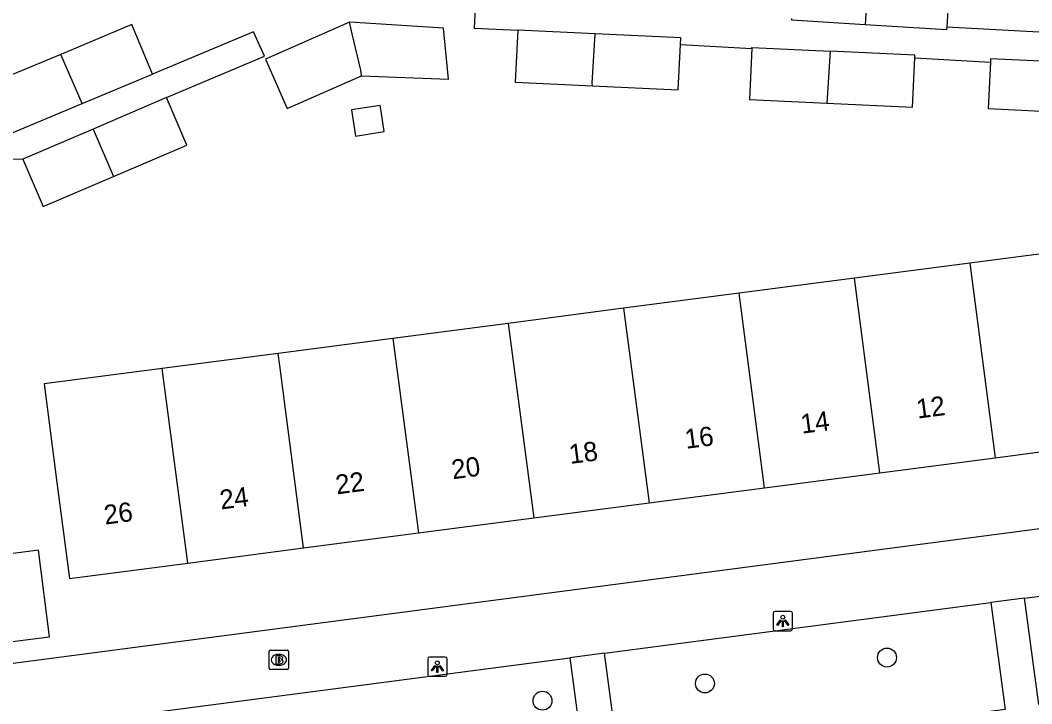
# Model space of a CAD drawing. Extents: x 162074 to 163034, y 381824 to 382557.
# Drawn here: x 162366.6 to 162418.9, y 382465.4 to 382500.7 of the extents above; entities that cross this region are included whole.
import ezdxf

# ---------------------------------------------------------------- set-up
doc = ezdxf.new("R2010")
doc.units = 0
for name, color, linetype in [('IMGEO_Boom', 7, 'Continuous'), ('IMGEO_Brandkraan', 7, 'Continuous'), ('IMGEO_Lichtpunt', 7, 'Continuous'), ('IMGEO_Pand', 7, 'Continuous'), ('IMGEO_Pand_nummerreeks', 7, 'Continuous'), ('IMGEO_Voetpad_open', 7, 'Continuous')]:
    doc.layers.add(name, color=color, linetype=linetype)

msp = doc.modelspace()

# ---------------------------------------------------------------- linework, layer by layer
at = {"layer": 'IMGEO_Boom'}
for centre in [(162411.408, 382467.759), (162401.998, 382466.42), (162393.602, 382465.53)]:
    msp.add_circle(centre, 0.489, dxfattribs=at)
at = {"layer": 'IMGEO_Brandkraan'}
for p, q in [((162379.475, 382467.216), (162379.475, 382468.068)), ((162379.55, 382468.142), (162380.402, 382468.142)), ((162380.476, 382468.068), (162380.476, 382467.216)), ((162379.963, 382467.922), (162379.988, 382467.922)), ((162380.402, 382467.142), (162379.55, 382467.142)), ((162379.986, 382467.362), (162379.961, 382467.362))]:
    msp.add_line(p, q, dxfattribs=at)
for points in [[(162379.475, 382467.216), (162379.475, 382468.068)], [(162379.55, 382468.142), (162380.402, 382468.142)], [(162380.476, 382468.068), (162380.476, 382467.216)], [(162379.823, 382467.842), (162379.823, 382467.442), (162380.036, 382467.442)], [(162380.054, 382467.842), (162379.823, 382467.842)], [(162380.002, 382467.761), (162379.948, 382467.761), (162379.948, 382467.685)], [(162379.948, 382467.685), (162380.001, 382467.685)], [(162380.01, 382467.609), (162379.948, 382467.609), (162379.948, 382467.528)], [(162379.948, 382467.528), (162380.01, 382467.528)], [(162380.402, 382467.142), (162379.55, 382467.142)]]:
    msp.add_lwpolyline(points, dxfattribs=at)
for centre, radius, start, end in [((162379.552, 382468.066), 0.0765, 91.552, 178.448), ((162379.552, 382468.066), 0.0765, 91.552, 178.448), ((162380.4, 382468.066), 0.0765, 1.552, 88.448), ((162380.4, 382468.066), 0.0765, 1.552, 88.448), ((162380.003, 382467.723), 0.0379, 267.8285, 90.9355), ((162380.011, 382467.568), 0.0404, 269.8759, 90.5077), ((162380.042, 382467.693), 0.251, 268.6676, 293.5347), ((162380.058, 382467.697), 0.145, 59.4692, 91.5367), ((162380.083, 382467.744), 0.0922, 285.5137, 58.1501), ((162380.088, 382467.552), 0.105, 301.3115, 78.989), ((162379.552, 382467.218), 0.0765, 181.552, 268.448), ((162379.552, 382467.218), 0.0765, 181.552, 268.448), ((162380.4, 382467.218), 0.0765, 271.552, 358.448), ((162380.4, 382467.218), 0.0765, 271.552, 358.448)]:
    msp.add_arc(centre, radius, start, end, dxfattribs=at)
for centre, major_axis, ratio, start_param, end_param in [((162379.962, 382467.642), (-0.387, 0.002), 0.722429, 4.712389, 7.853982), ((162379.987, 382467.642), (-0.39, 0.002), 0.717154, 1.570796, 4.712389)]:
    msp.add_ellipse(centre, major_axis=major_axis, ratio=ratio, start_param=start_param, end_param=end_param, dxfattribs=at)
at = {"layer": 'IMGEO_Lichtpunt'}
for p, q in [((162406.424, 382470.144), (162405.616, 382470.144)), ((162406.424, 382470.144), (162405.616, 382470.144)), ((162405.522, 382470.049), (162405.522, 382469.242)), ((162405.522, 382470.049), (162405.522, 382469.242)), ((162406.518, 382469.242), (162406.518, 382470.049)), ((162406.518, 382469.242), (162406.518, 382470.049)), ((162405.616, 382469.148), (162406.424, 382469.148)), ((162405.616, 382469.148), (162406.424, 382469.148)), ((162387.671, 382467.692), (162387.671, 382466.885)), ((162387.671, 382467.692), (162387.671, 382466.885)), ((162388.573, 382467.787), (162387.765, 382467.787)), ((162388.573, 382467.787), (162387.765, 382467.787)), ((162388.667, 382466.885), (162388.667, 382467.692)), ((162388.667, 382466.885), (162388.667, 382467.692)), ((162387.765, 382466.791), (162388.573, 382466.791)), ((162387.765, 382466.791), (162388.573, 382466.791))]:
    msp.add_line(p, q, dxfattribs=at)
for points in [[(162405.896, 382469.713), (162405.935, 382469.685), (162405.747, 382469.423), (162405.709, 382469.45), (162405.896, 382469.713)], [(162405.998, 382469.665), (162406.045, 382469.665), (162406.045, 382469.343), (162405.998, 382469.343), (162405.998, 382469.665)], [(162406.108, 382469.685), (162406.146, 382469.712), (162406.333, 382469.45), (162406.294, 382469.422), (162406.108, 382469.685)], [(162388.045, 382467.356), (162388.084, 382467.328), (162387.896, 382467.066), (162387.858, 382467.093), (162388.045, 382467.356)], [(162388.147, 382467.308), (162388.194, 382467.308), (162388.194, 382466.986), (162388.147, 382466.986), (162388.147, 382467.308)], [(162388.257, 382467.328), (162388.295, 382467.355), (162388.482, 382467.093), (162388.443, 382467.065), (162388.257, 382467.328)]]:
    msp.add_lwpolyline(points, dxfattribs=at)
for centre in [(162406.021, 382469.847), (162388.17, 382467.49)]:
    msp.add_circle(centre, 0.0994, dxfattribs=at)
for centre, start, end in [((162405.616, 382470.049), 90, 180), ((162405.616, 382470.049), 90, 180), ((162406.424, 382470.049), 0, 90), ((162406.424, 382470.049), 0, 90), ((162405.616, 382469.242), 180, 270), ((162405.616, 382469.242), 180, 270), ((162406.424, 382469.242), 270, 0), ((162406.424, 382469.242), 270, 360), ((162387.765, 382467.692), 90, 180), ((162387.765, 382467.692), 90, 180), ((162388.573, 382467.692), 0, 90), ((162388.573, 382467.692), 0, 90), ((162387.765, 382466.885), 180, 270), ((162387.765, 382466.885), 180, 270), ((162388.573, 382466.885), 270, 0), ((162388.573, 382466.885), 270, 360)]:
    msp.add_arc(centre, 0.0946, start, end, dxfattribs=at)
at = {"layer": 'IMGEO_Pand'}
for points in [[(162410.442, 382503.127), (162410.281, 382500.473)], [(162410.442, 382503.127), (162414.648, 382502.872), (162414.497, 382500.375)], [(162373.452, 382497.926), (162372.384, 382500.48), (162368.715, 382498.945)], [(162383.62, 382500.609), (162379.291, 382498.702), (162380.414, 382496.152), (162384.248, 382497.84)], [(162384.248, 382497.84), (162388.743, 382497.665), (162388.478, 382500.298), (162383.638, 382500.617), (162383.62, 382500.609)], [(162384.248, 382497.84), (162384.214, 382498.119), (162383.765, 382500), (162383.62, 382500.609)], [(162410.281, 382500.473), (162406.483, 382500.704), (162406.489, 382500.801)], [(162414.497, 382500.375), (162414.488, 382500.219), (162410.281, 382500.473)], [(162392.32, 382500.197), (162392.193, 382497.512), (162396.193, 382497.323)], [(162396.318, 382500.008), (162392.32, 382500.197)], [(162396.193, 382497.323), (162396.175, 382497.45), (162396.318, 382500.008)], [(162400.733, 382499.462), (162400.749, 382499.798), (162396.318, 382500.008)], [(162396.193, 382497.323), (162400.622, 382497.114), (162400.733, 382499.462)], [(162368.715, 382498.945), (162365.914, 382497.774), (162365.006, 382497.395), (162366.074, 382494.84)], [(162369.808, 382496.402), (162368.715, 382498.945)], [(162404.418, 382499.25), (162404.293, 382496.611), (162408.302, 382496.421)], [(162404.418, 382499.25), (162404.42, 382499.295), (162408.471, 382499.104)], [(162408.471, 382499.104), (162408.302, 382496.421)], [(162412.843, 382498.764), (162412.849, 382498.896), (162408.471, 382499.104)], [(162408.302, 382496.421), (162412.722, 382496.212), (162412.843, 382498.764)], [(162416.755, 382498.539), (162416.641, 382496.139), (162420.749, 382495.945)], [(162420.871, 382498.523), (162416.763, 382498.717), (162416.755, 382498.539)], [(162369.808, 382496.402), (162373.452, 382497.926)], [(162366.074, 382494.84), (162369.808, 382496.402)], [(162374.163, 382496.707), (162370.375, 382495.082)], [(162371.428, 382492.628), (162375.216, 382494.253), (162374.163, 382496.707)], [(162383.738, 382496.071), (162383.944, 382494.722), (162385.422, 382494.948), (162385.261, 382496), (162385.215, 382496.297), (162383.738, 382496.071)], [(162370.375, 382495.082), (162366.744, 382493.524)], [(162370.375, 382495.082), (162371.428, 382492.628)], [(162366.744, 382493.524), (162367.796, 382491.071), (162371.428, 382492.628)], [(162421.643, 382488.929), (162415.682, 382488.151)], [(162415.682, 382488.151), (162409.72, 382487.373)], [(162415.682, 382488.151), (162416.995, 382478.094)], [(162409.72, 382487.373), (162403.759, 382486.595)], [(162411.033, 382477.316), (162409.72, 382487.373)], [(162403.759, 382486.595), (162397.797, 382485.817)], [(162405.072, 382476.538), (162403.759, 382486.595)], [(162397.797, 382485.817), (162391.836, 382485.039)], [(162397.797, 382485.817), (162399.11, 382475.759)], [(162391.836, 382485.039), (162385.874, 382484.261)], [(162391.836, 382485.039), (162393.149, 382474.981)], [(162385.874, 382484.261), (162379.938, 382483.486)], [(162385.874, 382484.261), (162387.187, 382474.203)], [(162379.938, 382483.486), (162373.951, 382482.705)], [(162381.247, 382473.428), (162380.02, 382482.853), (162379.938, 382483.486)], [(162373.951, 382482.705), (162367.839, 382481.907), (162368.505, 382476.807), (162369.152, 382471.849), (162375.264, 382472.647)], [(162375.264, 382472.647), (162373.951, 382482.705)], [(162416.995, 382478.094), (162422.956, 382478.872)], [(162411.033, 382477.316), (162416.995, 382478.094)], [(162405.072, 382476.538), (162411.033, 382477.316)], [(162399.11, 382475.759), (162405.072, 382476.538)], [(162393.149, 382474.981), (162399.11, 382475.759)], [(162387.187, 382474.203), (162393.149, 382474.981)], [(162381.247, 382473.428), (162387.187, 382474.203)], [(162365.36, 382468.479), (162368.129, 382468.84), (162367.545, 382473.312), (162364.776, 382472.95), (162365.36, 382468.479)], [(162375.264, 382472.647), (162381.247, 382473.428)]]:
    msp.add_lwpolyline(points, dxfattribs=at)
at = {"layer": 'IMGEO_Voetpad_open'}
for points in [[(162390.14, 382501.726), (162390.073, 382500.303), (162392.32, 382500.197)], [(162374.163, 382496.707), (162379.229, 382498.843), (162378.672, 382500.109), (162373.452, 382497.926)], [(162414.497, 382500.375), (162421.163, 382500.014)], [(162400.733, 382499.462), (162404.418, 382499.25)], [(162412.843, 382498.764), (162416.755, 382498.539)], [(162363.092, 382494.628), (162364.021, 382493.592), (162366.744, 382493.524)], [(162441.501, 382477.324), (162364.52, 382467.221), (162358.274, 382466.401), (162352.438, 382465.635)], [(162438.951, 382473.504), (162439.679, 382467.926), (162419.261, 382465.333), (162418.51, 382470.827)], [(162418.51, 382470.827), (162438.951, 382473.504)], [(162416.769, 382470.6), (162417.516, 382465.082), (162397.548, 382462.43), (162396.812, 382467.987)], [(162396.812, 382467.987), (162416.769, 382470.6)], [(162418.51, 382470.827), (162416.769, 382470.6)], [(162396.812, 382467.987), (162395.012, 382467.752)], [(162395.012, 382467.752), (162395.761, 382462.198), (162373.908, 382459.306), (162373.173, 382464.892)], [(162373.173, 382464.892), (162395.012, 382467.752)]]:
    msp.add_lwpolyline(points, dxfattribs=at)

# ---------------------------------------------------------------- texts
at = {"layer": 'IMGEO_Pand_nummerreeks'}
for s, p in [('12', (162412.992, 382480.112)), ('14', (162407.008, 382479.332)), ('16', (162401.022, 382478.55)), ('18', (162395.039, 382477.769)), ('20', (162388.962, 382476.976)), ('22', (162382.97, 382476.194)), ('24', (162376.986, 382475.413)), ('26', (162371, 382474.631))]:
    msp.add_text(s, height=1, rotation=7.4369, dxfattribs=at).set_placement(p)

doc.saveas('drawing.dxf')
